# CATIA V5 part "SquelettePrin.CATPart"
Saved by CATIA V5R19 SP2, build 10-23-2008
Part number: SquelettePrin
Publications: "Plan.1", "Point.1", "LongueurAB", "largeur", "AxeRoue", "LongueurBD", "LongueurCD", "RayonTrou", "LargeurBCD"
Bounding box of the stored display mesh (mm): x -20 to 20, y 0 to 0, z 0 to 0
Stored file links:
  D:\France\IFMA\IAO\Projet\SquelettePrin.CATPart
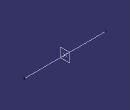
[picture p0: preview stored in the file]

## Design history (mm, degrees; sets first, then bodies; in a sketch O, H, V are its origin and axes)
Parameters
  LongueurAB = 180 mm
  Largeur = 10 mm
  LongueurBD = 40 mm
  LongueurCD = 30 mm
  RayonTrou = 5 mm
  LargeurBCD = 10 mm
Set1
  Plane1 "Plane.1": type Offset, RefPlane yz-plane, Offset 0
  Point1 "Point.1": (0, 0, 0)
  Line1: type PtDir, RefPoint Point1, Direction (1, 0, 0), Start -20, End 20
Body1 (main body)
